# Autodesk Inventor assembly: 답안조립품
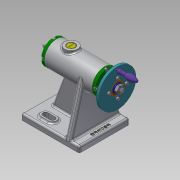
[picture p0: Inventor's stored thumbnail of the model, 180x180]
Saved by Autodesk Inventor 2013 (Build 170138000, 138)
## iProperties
Created: 2019-10
Part Number: 답안조립품
Document SubType Name: Assembly
Designer: Administrator
Author: Administrator
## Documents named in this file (18)
- C:\Users\Administrator\Desktop\491004V1023\답안조립품.iam
- C:\Users\Administrator\Desktop\491004V1023\본체.ipt
- C:\Users\Administrator\Desktop\491004V1023\나사.ipt
- C:\Users\Administrator\Desktop\491004V1023\나사축.ipt
- C:\Users\Administrator\Desktop\491004V1023\너트 M8.ipt
- C:\Users\Administrator\Desktop\491004V1023\돌림판.ipt
- C:\Users\Administrator\Desktop\491004V1023\멈춤나사 M3.ipt
- C:\Users\Administrator\Desktop\491004V1023\볼트 M3.ipt
- C:\Users\Administrator\Desktop\491004V1023\부시.ipt
- C:\Users\Administrator\Desktop\491004V1023\센터.ipt
- C:\Users\Administrator\Desktop\491004V1023\센터홀더.ipt
- C:\Users\Administrator\Desktop\491004V1023\슬리브.ipt
- C:\Users\Administrator\Desktop\491004V1023\와셔.ipt
- C:\Users\Administrator\Desktop\491004V1023\중공축.ipt
- C:\Users\Administrator\Desktop\491004V1023\커버.ipt
- C:\Users\Administrator\Desktop\491004V1023\키 4 x 4 x 10.ipt
- C:\Users\Administrator\Desktop\491004V1023\플랜지.ipt
- C:\Users\Administrator\Desktop\491004V1023\핸들.ipt
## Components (2 placed, 2 different names)
1. 플랜지:1
2. 핸들:1 — 플러쉬:1
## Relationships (1: Flush 1)
- 플러쉬:1 [Flush]: 핸들:1
